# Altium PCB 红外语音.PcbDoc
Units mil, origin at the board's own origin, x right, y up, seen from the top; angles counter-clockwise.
Board outline 3936.84 x 3930.7 mil, 2 copper layers (Top Layer, Bottom Layer); 44 components, 33 nets, 149 pads, 170 vias.
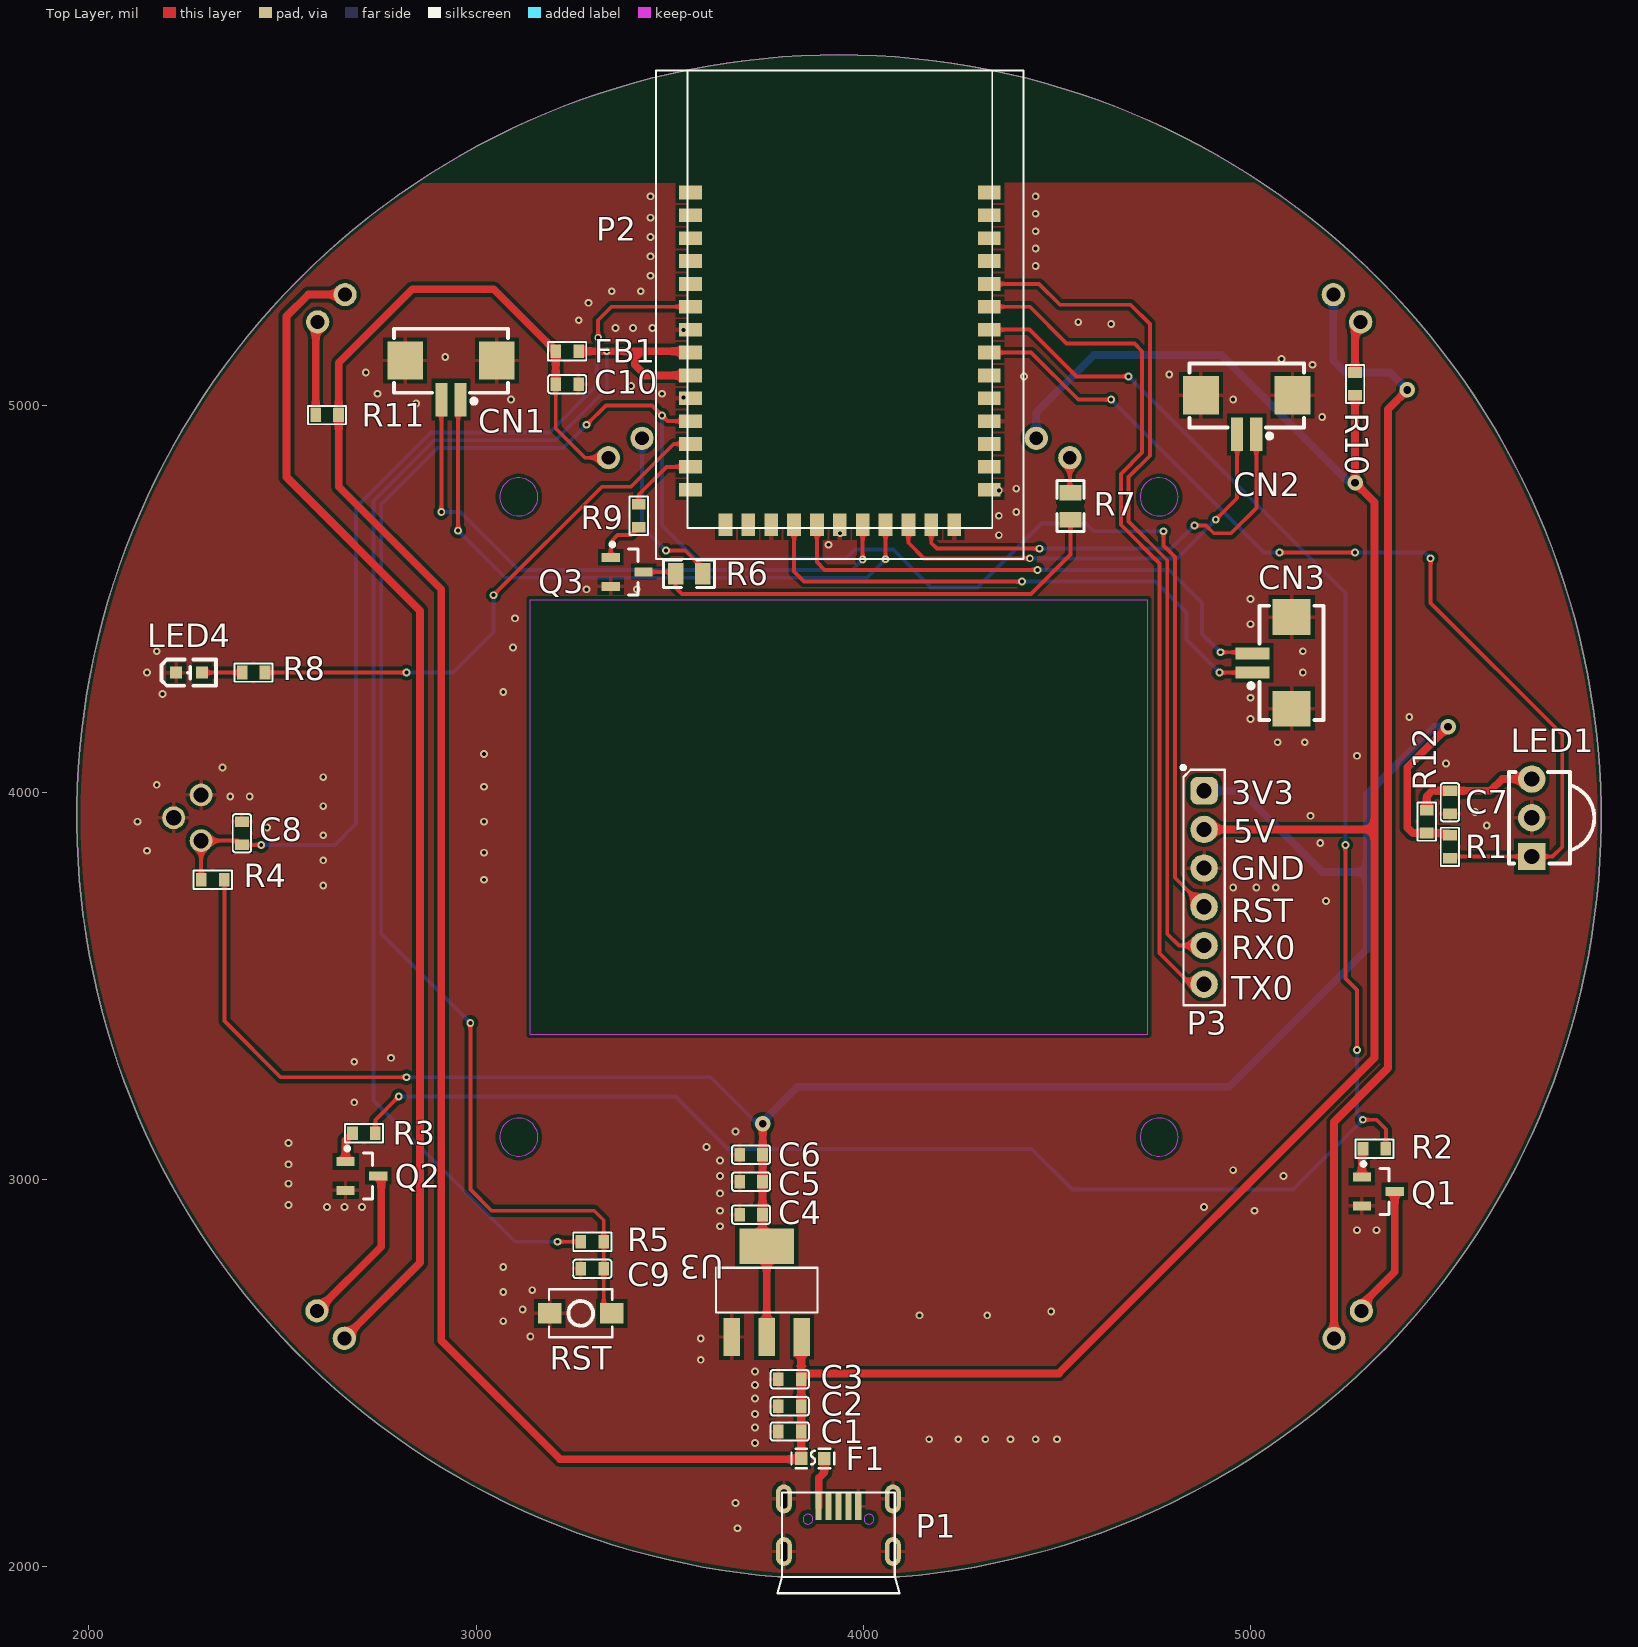
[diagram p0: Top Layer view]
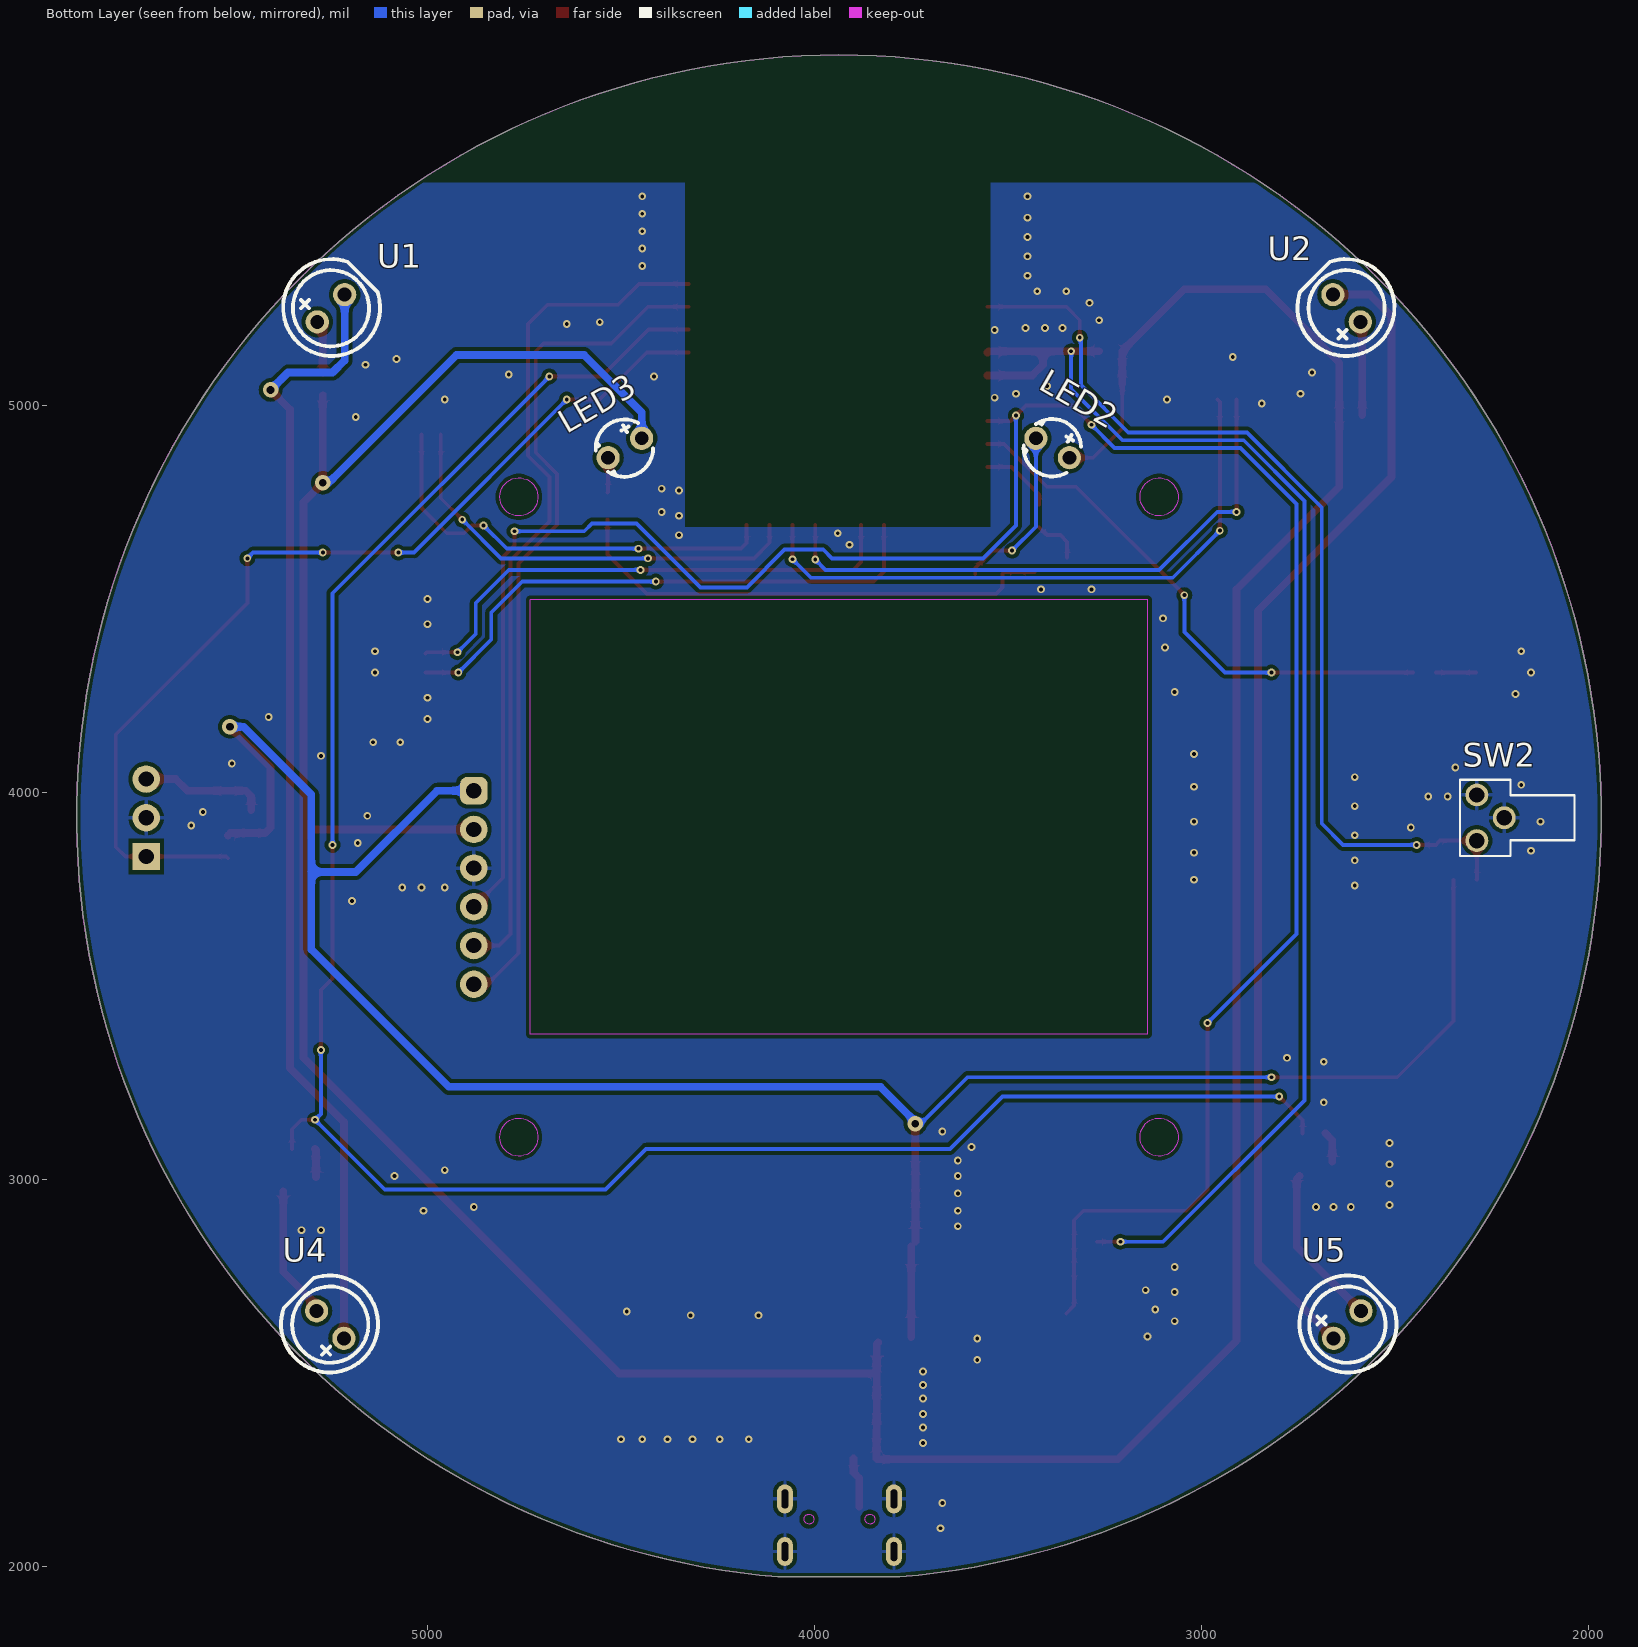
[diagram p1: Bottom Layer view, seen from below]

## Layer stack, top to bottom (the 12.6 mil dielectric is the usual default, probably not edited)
Top Solder: solder mask 0.4, Solder Resist, Dk 3.5
Top Layer: signal copper 1.4
Dielectric 1: dielectric 12.6, FR-4, Dk 4.8
Bottom Layer: signal copper 1.4
Bottom Solder: solder mask 0.4, Solder Resist, Dk 3.5

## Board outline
3779.51,1974.81 cw(c3937.01,3937.01) 4094.5,1974.81 4094.49,1974.81

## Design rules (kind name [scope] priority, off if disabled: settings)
Clearance [All] p1: gap=10
PolygonConnect [IsVia] p1: connectstyle=Direct reliefconductorwidth=10 reliefentries=4 polygonreliefangle="90 Angle" airgapwidth=10
PolygonConnect PolygonConnect_1 [All] p2: connectstyle=Relief reliefconductorwidth=10 reliefentries=4 polygonreliefangle="90 Angle" airgapwidth=10
RoutingVias [All] p1: holewidth=28 width=50 viastyle="Through Hole" minholewidth=28 minwidth=50 maxholewidth=28 maxwidth=50
SolderMaskExpansion [All] p1: expansion=4
Width [All] p1: maxlimit=50 minlimit=10 preferedwidth=10
30 further rules are at their usual default settings.

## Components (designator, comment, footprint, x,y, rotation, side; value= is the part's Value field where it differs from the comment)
C1 "22uF/6.3V" C0603_GRM18 3810,2350 r0 top
C2 "10uF/6.3V" C0603_GRM18 3810,2415 r0 top
C3 "100nF/25V" C0603_GRM18 3810,2485 r0 top
C4 "10uF/6.3V" C0603_GRM18 3710,2910 r0 top
C5 "100nF/25V" C0603_GRM18 3710,2995 r0 top
C6 "22uF/6.3V" C0603_GRM18 3710,3065 r0 top
C7 "4.7uF/10V" C0603_GRM18 5515,3975 r90 top
C8 "0.1uF/16V" C0603_GRM18 2395,3895 r270 top
C9 "0.1uF/16V" C0603_GRM18 3300,2770 r0 top
C10 "22uF/6.3V" C0603_GRM18 3235,5055 r180 top
CN1 "HC-1.25-2PWT" CONN-SMD_2P-P1.25-HC-1.25-2PWT 2935,5090 r180 top
CN2 "HC-1.25-2PWT" CONN-SMD_2P-P1.25-HC-1.25-2PWT 4990,5000 r180 top
CN3 "HC-1.25-2PWT" CONN-SMD_2P-P1.25-HC-1.25-2PWT 5080,4335 r90 top
F1 "BSMD0603L-150" F0603 3870,2280 r180 top
FB1 "100Mhz/1500mA" FB0603-H95 3235,5140 r0 top
LED1 "IRM-3638T-X" OPTO-TH_3P_IRM-36XXT 5775,3935 r90 top locked
LED2 "TZ-L2-03YYBW4TDJ40-001" LED-TH_BD3.8-P2.54-RD 3385,4890 r210 bottom locked
LED3 "TZ-L2-03YYBW4TDJ40-001" LED-TH_BD3.8-P2.54-RD 4490,4890 r150 bottom locked
LED4 "FC-F1608BK-470H5" LED0603-R-RD 2257.5,4310 r0 top
P1 "E-SMXXXXX" MIRCOUSB_5PIN 3935.75,2107.91 r0 top locked
P2 "VWRK2_ES-PCBA" VWXR2-ES-PCBA 3939.17,5120.87 r0 top locked
P3 "PH2.54-1x6p" HDR254-1x6-M-H885 4880,3755 r270 top
Q1 "S8050" SOT23-3 5330,2970 r0 top
Q2 "S8050" SOT23-3 2705,3010 r0 top
Q3 "S8050" SOT23-3 3390,4570 r0 top
R1 "10k" R0603 5515,3860 r270 top
R2 "1K/1%" R0603 5320,3080 r180 top
R3 "1K/1%" R0603 2710,3120 r180 top
R4 "10k/1%" R0603 2319.53,3775 r0 top
R5 "10k/1%" R0603 3300,2840 r180 top
R6 "120R" R0805 3550,4565 r0 top
R7 "120R" R0805 4535,4740 r90 top
R8 "1K/1%" R0603 2425,4310 r180 top
R9 "1K/1%" R0603 3420,4715 r270 top
R10 "20R" R0603 5270,5055.47 r270 top
R11 "20R" R0603 2615,4975 r0 top
R12 "47R" R0603 5455,3925 r270 top
RST "TS-1088-AR02016" SW-SMD_L4.0-W2.9-LS5.0 3270,2655 r0 top (schematic designator SW1)
SW2 "TS4570E-250AH" SW-3-4.5X4.5X7 2270,3935 r270 bottom locked
U1 "IR333-A_C264290" LED-TH_BD6.2-P2.54-FD 5250,5250 r135 bottom locked
U2 "IR333-A_C264290" LED-TH_BD6.2-P2.54-FD 2625,5250 r45 bottom
U3 "AMS1117-3.3" SOT-223-3_L6.5-W3.4-P2.30-LS7.0-BR 3805,2765 r270 top
U4 "IR333-A_C264290" LED-TH_BD6.2-P2.54-FD 5250,2625 r45 bottom locked
U5 "IR333-A_C264290" LED-TH_BD6.2-P2.54-FD 2625,2625 r135 bottom locked

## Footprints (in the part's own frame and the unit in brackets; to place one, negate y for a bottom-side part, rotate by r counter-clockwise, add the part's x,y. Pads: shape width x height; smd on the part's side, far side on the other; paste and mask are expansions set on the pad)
C0603_GRM18 [mm] "适用Murata GRM15封装"
  rect 0.7x0.9 smd paste+0 mask+0.051: 1(-0.75,0) 2(0.75,0)
  Top Layer pour cut-out: -0.254,0.602 0.254,0.602 0.254,-0.602 -0.254,-0.602
  silkscreen extent -1.25,-0.6 1.25,0.6, body extent -0.8,-0.4 0.8,0.4, height 0.8
CONN-SMD_2P-P1.25-HC-1.25-2PWT [mm]
  rect 0.8x2.2 smd: 1(-0.625,1.905) 2(0.625,1.905)
  rect 2.35x2.5 smd: 3(-3.005,-0.665) 4(3.005,-0.665)
  silkscreen extent -3.75,-2.74 3.75,2.16
F0603 [mil]
  rect 31.75x34.02 smd: 1(-29.2,0) 2(30.11,0)
  silkscreen extent -55,-25 55,25
FB0603-H95 [mm]
  rect 0.7x0.9 smd paste+0 mask+0.051: 1(-0.75,0) 2(0.75,0)
  Top Layer pour cut-out: -0.313,0.602 -0.313,-0.602 0.315,-0.602 0.315,0.602
  silkscreen extent -1.25,-0.6 1.25,0.6, body extent -0.9,-0.48 0.9,0.47, height 0.97
HDR254-1x6-M-H885 [mm] "Connector; Header; 1x6 Position"
  rrect50% 1.8x1.8 hole 1 mask+0.051: 1(-6.35,0)
  round 1.8 hole 1 mask+0.051: 2(-3.81,0) 3(-1.27,0) 4(1.27,0) 5(3.81,0) 6(6.35,0)
  silkscreen extent -7.98,-1.49 7.72,1.35, body extent -7.62,-1.27 7.62,1.27, height 8.54
LED0603-R-RD [mm]
  rect 0.8x0.8 smd: 1(0.876,0) 2(-0.826,0)
  silkscreen extent -1.79,-0.86 1.79,0.86
LED-TH_BD3.8-P2.54-RD [mil]
  round 60 hole 35.43: 1(-50,0) 2(50,0)
  silkscreen extent -68,-74 63,74
LED-TH_BD6.2-P2.54-FD [mil]
  round 60 hole 36: 1(-48.68,0) 2(51.32,0)
  silkscreen extent -121,-125 116,125
MIRCOUSB_5PIN [mm]
  rect 0.4x1.778 smd mask+0.051: 1(-1.3,1.225) 2(-0.65,1.225) 3(0,1.225) 4(0.65,1.225) 5(1.3,1.225)
  oval 1.05x1.9 hole 0.45 slot 1.25 at 90 deg: G1(-3.575,1.725) G2(-3.575,-1.725) G3(3.575,-1.725) G4(3.575,1.725)
  Keep-Out Layer circle w0.076: c2,0.4 r0.325
  Keep-Out Layer circle w0.076: c-2,0.4 r0.325
  silkscreen extent -4,-4.46 4,2.14
OPTO-TH_3P_IRM-36XXT [mm]
  rect 1.8x1.8 hole 1: 1(-2.54,1.237)
  round 1.8 hole 1: 2(0,1.237) 3(2.54,1.237)
  silkscreen extent -3,-2.86 3,2.74
R0603 [mm]
  rect 0.7x0.9 smd paste+0 mask+0.051: 1(-0.75,0) 2(0.75,0)
  Top Layer pour cut-out: -0.315,-0.602 -0.315,0.602 0.324,0.602 0.324,-0.602
  silkscreen extent -1.25,-0.6 1.25,0.6, body extent -0.8,-0.4 0.8,0.4, height 0.45
R0805 [mil]
  rect 40x56 smd mask+2.01: 1(-35,0) 2(35,0)
  Top Layer pour cut-out: -19.69,-35.43 -19.69,35.43 19.69,35.43 19.69,-35.43
  silkscreen extent -66,-35 66,35, body extent -39,-25 39,25, height 22
SOT23-3 [mm] "SOT23"
  rect 1.2x0.6 smd mask+0.051: 1(-1.075,0.95) 2(-1.075,-0.95) 3(1.075,0)
  silkscreen extent -1.1,-1.5 0.7,1.92, body extent -1.4,-1.45 1.4,1.45, height 1.2
SOT-223-3_L6.5-W3.4-P2.30-LS7.0-BR [mm]
  rect 2.5x1.1 smd: 1(4.34,-3.684) 2(4.34,-1.384) 3(4.34,0.916)
  rect 2.34x3.6 smd: 4(-1.6,-1.384)
  silkscreen extent -0.2,-4.71 2.74,1.94
SW-3-4.5X4.5X7 [mm] "轻触开关-4.5x4.5x7mm-DIP 3pin-L=4mm-卧式"
  round 1.5 hole 1: 1(-1.5,-0.498) 2(1.5,-0.498) 3(0,1.302)
  silkscreen extent -2.5,-1.6 2.5,5.91, body extent -2.31,-1.46 2.3,5.54, height 4.48
SW-SMD_L4.0-W2.9-LS5.0 [mm]
  rect 1.53x1.36 smd: 1(-2.035,0) 2(2.035,0)
  silkscreen extent -2.08,-1.58 2.08,1.58
VWXR2-ES-PCBA [mm]
  rect 1.5x0.9 smd mask+0.051: 1(-9.8,10.9) 2(-9.8,9.4) 3(-9.8,7.9) 4(-9.8,6.4) 5(-9.8,4.9) 6(-9.8,3.4) 7(-9.8,1.9) 8(-9.8,0.4) 9(-9.8,-1.1) 10(-9.8,-2.6) 11(-9.8,-4.1) 12(-9.8,-5.6) 13(-9.8,-7.1) 14(-9.8,-8.6) 26(9.8,-8.6) 27(9.8,-7.1) 28(9.8,-5.6) 29(9.8,-4.1) 30(9.8,-2.6) 31(9.8,-1.1) 32(9.8,0.4) 33(9.8,1.9) 34(9.8,3.4) 35(9.8,4.9) 36(9.8,6.4) 37(9.8,7.9) 38(9.8,9.4) 39(9.8,10.9)
  rect 0.9x1.5 smd mask+0.051: 15(-7.5,-10.9) 16(-6,-10.9) 17(-4.5,-10.9) 18(-3,-10.9) 19(-1.5,-10.9) 20(0,-10.9) 21(1.5,-10.9) 22(3,-10.9) 23(4.5,-10.9) 24(6,-10.9) 25(7.5,-10.9)
  silkscreen extent -12.05,-13.15 12.05,18.9, body extent -10,-11.1 10,18.9, height 3.6

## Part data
C1 C6 C10: library part 1.02.05.00885, "无极性电容"
C2 C4: library part 1.02.05.00861, "无极性电容"
C3 C5: library part 1.02.05.00915, "无极性电容"
C7: library part 1.02.05.00710, "无极性电容"
C8 C9: library part 1.02.05.00869, "无极性电容"
FB1: library part 1.04.03.00007, "磁珠"
P1: library part 1.14.03.00024, "USB"
P2: library part 2.05.04.00192
P3: library part 1.14.01.00027, "单排6pin"
Q1 Q2 Q3: library part 1.06.07.00232, "NPN  三极管"
R1: library part 1.01.01.01043, "电阻"
R2 R3 R8 R9: library part 1.01.01.00734, "电阻"
R4 R5: library part 1.01.01.01140, "电阻"
R6 R7: library part 1.01.01.01495, "电阻"
R10 R11: library part 1.01.01.01068, "电阻"
R12: library part 1.01.01.01739, "电阻"
SW2: library part 1.14.10.00254

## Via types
v1: diameter 20, hole 10, Top Layer to Bottom Layer, 166 vias
v2: diameter 40, hole 20, Top Layer to Bottom Layer, 4 vias

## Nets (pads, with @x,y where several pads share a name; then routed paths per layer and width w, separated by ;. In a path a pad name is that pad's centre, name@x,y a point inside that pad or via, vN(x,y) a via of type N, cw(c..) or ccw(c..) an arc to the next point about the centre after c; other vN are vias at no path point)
3V3: C4.2 C5.2 C6.2 P3.1 R1.1 R4.2 R12.2 U3.2 U3.4 | length 5764.5
  Top Layer w10: R4.2 2350,3774.06 2350,3410 2495,3265 v1(2820,3265)
  Top Layer w20: U3.4@3739.53,2840.47 3739.53,3030 3740,3030.47 v2(3740,3145) ; U3.2 U3.4 ; v2(5510,4170) 5405,4065 5405,3910 5419.53,3895.47 R12.2 5509.06,3895.47 R1.1
  Bottom Layer w10: v1(2820,3265) 3605,3265 3725,3145 v2(3740,3145)
  Bottom Layer w20: v2(3740,3145) 3740,3150 3830,3240 4945,3240 5300,3595 5300,3795 ; P3.1 4975,4005 5185,3795 5300,3795 ; v2(5510,4170) 5475,4170 5300,3995 5300,3795
5V: C1.2 C2.2 C3.2 C10.2 F1.2 FB1.1 LED2.2 LED3.2 P3.2 R10.2 R11.2 U3.3 | length 10150.2
  Top Layer w10: C10.2 3205.47,4940.47 3280.94,4865 LED2.2 ; R10.2@5265.94,5030 R10.2
  Top Layer w20: C10.2 FB1.1 3045.47,5300 2835,5300 2645,5110 2645,4790 2910,4525 2910,2585 3216.71,2278.29 3838.18,2278.29 F1.2 3839.89,2354.64 3839.53,2355 C3.2@3839.53,2500 ; U3.3@3835.55,2580 3839.53,2576.02 C3.2@3839.53,2500 ; P3.2 5320,3905 ; R10.2 v2(5270,4800) 5320,4750 5320,3905 ; C3.2@3839.53,2500 4505,2500 5320,3315 5320,3905
  Bottom Layer w10: v2@5255,4800 v2(5270,4800)
  Bottom Layer w20: LED3.2 4446.7,4981.7 4595,5130 4925,5130 v2@5255,4800
GND: C1.1 C2.1 C3.1 C4.1 C5.1 C6.1 C7.1 C8.1 C9.1 C10.1 CN1.3 CN1.4 CN2.3 CN2.4 CN3.3 CN3.4 LED1.2 LED4.2 P1.5 P1.G1 P1.G2 P1.G3 P1.G4 P2.7 P2.10 P2.17 P2.20 P2.25 P2.26 P2.29 P3.3 Q1.2 Q2.2 Q3.2 RST.1 SW2.1 SW2.3 U3.1
  other v1: 3675,2100 3670,2165 3720,2320 4170,2330 4245,2330 4315,2330 4380,2330 4445,2330 4500,2330 3720,2360 3720,2395 3720,2435 3720,2470 3720,2505 3580,2535 3580,2590 3140,2595 3070,2635 4145,2650 4320,2650 4485,2660 3120,2665 3070,2710 3145,2715 3070,2775 5275,2870 5325,2870 3630,2880 3630,2920 5010,2920 2615,2930 2660,2930 2705,2930 4880,2930 2515,2935 3630,2965 2515,2990 3630,3010 5085,3010 4955,3025 2515,3040 3630,3050 3595,3085 2515,3095 3670,3125 2685,3200 2685,3305 2780,3315 5195,3720 4955,3755 5015,3755 5065,3755 2605,3760 3020,3775 2605,3825 3020,3845 2150,3850 5180,3870 2605,3890 2460,3910 5610,3915 2125,3925 3020,3925 5155,3940 5580,3950 2605,3965 2365,3990 2415,3990 3020,4015 2175,4020 2605,4040 2345,4065 5505,4075 5275,4095 3020,4100 5070,4130 5140,4130 5000,4190 5410,4195 5000,4245 2190,4255 3070,4260 2150,4310 5135,4310 2175,4365 5135,4365 3095,4375 5000,4435 3100,4450 5000,4500 3285,4525 3415,4525 3910,4640 4350,4665 3940,4670 4350,4715 4395,4725 4350,4780 4395,4785 5185,4970 2845,5005 3090,5015 4955,5015 3535,5020 2745,5030 3480,5030 3400,5050 4415,5075 4790,5080 2715,5085 5160,5105 5080,5120 2920,5125 3535,5195 3360,5200 3405,5200 3455,5200 4640,5210 4555,5215 3265,5220 3290,5265 3350,5295 3425,5295 3450,5335 4445,5360 3450,5385 4445,5405 3450,5435 4445,5450 3450,5485 4445,5495 3450,5540 4445,5540
IR_RX: LED1.1 P2.32 R1.2 | length 2548.3
  Top Layer w10: P2.32 4433.39,5136.61 4555,5015 v1(4640,5015) ; v1(5075,4620) v1(5270,4620) ; v1(5465,4605) 5465,4490 5805,4150 5805,3860 5780,3835 LED1.1 5519.53,3835 R1.2
  Bottom Layer w10: v1(4640,5015) 5035,4620 v1(5075,4620) ; v1(5270,4620) 5450,4620 v1(5465,4605)
IR_TX: P2.33 R2.1 R3.1 | length 5484.8
  Top Layer w10: R3.1 2739.53,3154.53 v1(2800,3215) ; P2.33 4429.33,5195.67 4550,5075 v1(4685,5075) ; v1(5245,3865) 5245,3520 5275,3490 v1(5275,3335) ; v1(5290,3155) 5325,3155 5349.53,3130.47 R2.1
  Bottom Layer w10: v1(2800,3215) 3515,3215 3650,3080 4435,3080 4540,2975 5110,2975 v1(5290,3155) 5275,3170 v1(5275,3335) ; v1(4685,5075) 5245,4515 v1(5245,3865)
MIC1+: CN1.1 P2.22 | length 1604
  Top Layer w10: v1(2953.36,4676.64) 2953.36,5008.75 CN1.1 ; v1(4057.28,4602.72) P2.22
  Bottom Layer w10: v1(2953.36,4676.64) 3075,4555 4009.57,4555 v1(4057.28,4602.72)
MIC1-: CN1.2 P2.21 | length 1541.6
  Top Layer w10: v1(2910,4725) 2910,5014.61 CN1.2 ; v1(3998.23,4601.77) P2.21
  Bottom Layer w10: v1(2910,4725) 2960,4725 3110,4575 3971.46,4575 v1(3998.23,4601.77)
MIC2+: CN2.1 P2.24 | length 1143
  Top Layer w10: P2.24 4175.39,4644.61 4190,4630 v1(4455,4630) ; v1(4855,4690) 4885,4690 4905,4670 4950,4670 5015,4735 5015,4924.61 CN2.1
  Bottom Layer w10: v1(4455,4630) 4795,4630 v1(4855,4690)
MIC2-: CN2.2 P2.23 | length 1141.1
  Top Layer w10: P2.23 4116.34,4645.38 4156.72,4605 v1(4430,4605) ; v1(4910,4705) 4965.39,4760.39 CN2.2
  Bottom Layer w10: v1(4430,4605) 4810,4605 v1(4910,4705)
NetC7_2: C7.2 LED1.3 R12.1 | length 325.4
  Top Layer w20: R12.1 5455,3990 5469.53,4004.53 C7.2 5619.53,4004.53 5650,4035 LED1.3
NetF1_1: F1.1 P1.1 | length 129.9
  Top Layer w20: P1.1 3884.57,2229.57 3899.2,2244.2 F1.1
NetLED2_1: LED2.1 R6.2 | length 444.2
  Top Layer w10: v1(3490,4625) 3540,4625 3585,4580 R6.2
  Bottom Layer w10: LED2.1 3428.3,4686.7 v1(3490,4625)
NetLED3_1: LED3.1 R7.2 | length 90.7
  Top Layer w10: LED3.1 4533.3,4776.7 R7.2
NetLED4_1: LED4.1 R8.2 | length 103.5
  Top Layer w10: LED4.1 R8.2
NetQ1_1: Q1.1 R2.2 | length 73.8
  Top Layer w20: Q1.1 5287.68,3077.2 R2.2
NetQ1_3: Q1.3 U4.2 | length 344.3
  Top Layer w20: U4.2 5286.29,2676.29 5372.32,2762.32 Q1.3
NetQ2_1: Q2.1 R3.2 | length 80
  Top Layer w20: Q2.1 2662.68,3102.2 R3.2
NetQ2_3: Q2.3 U5.2 | length 420.8
  Top Layer w20: U5.2 2755,2827.57 2755,3002.32 Q2.3
NetQ3_1: Q3.1 R9.2 | length 128.3
  Top Layer w10: Q3.1 3347.68,4647.68 3365,4665 3399.53,4665 R9.2
NetQ3_3: Q3.3 R6.1 R7.1 | length 1278.8
  Top Layer w10: Q3.3 3510,4570 R6.1 3515,4530 3531.72,4513.28 4433.28,4513.28 4535,4615 R7.1
NetR10_1: R10.1 U1.1 | length 135
  Top Layer w10: U1.1@5259.42,5215.58 5259.42,5205.22 U1.1@5270,5194.64
  Top Layer w20: R10.1 U1.1@5270,5194.64
NetR11_1: R11.1 U2.1 | length 242.7
  Top Layer w10: U2.1@2585.47,5210.47 U2.1
  Top Layer w20: R11.1 U2.1@2585.47,5210.47
NetU1_2: U1.2 U4.1 | length 2920.8
  Top Layer w20: U4.1 5215.58,3149.42 5355,3288.85 5355,4990 v2(5405,5040)
  Bottom Layer w20: U1.2 5213.71,5116.29 5245,5085 5360,5085 v2(5405,5040)
NetU2_2: U2.2 U5.1 | length 3037.9
  Top Layer w20: U5.1 2855,2786.15 2855,4470 2510,4815 2510,5230 2566.29,5286.29 U2.2
PB17: C8.2 P2.6 R4.1 SW2.2 | length 2520
  Top Layer w10: R4.1 2289.61,3775.39 SW2.2 2384.53,3875.94 C8.2 2395.47,3865 v1(2445,3865) ; v1(3315,5175) 3315,5220 3349.72,5254.72 P2.6
  Bottom Layer w10: v1(2445,3865) 2635,3865 2690,3920 2690,4736.57 2883.43,4930 3190,4930 3312.26,5052.26 3312.26,5172.26 v1(3315,5175)
PWM0: P2.12 R8.1 | length 1399
  Top Layer w10: R8.1 v1(2820,4310) ; v1(3045,4510) 3325,4790 3400,4790 3510.39,4900.39 P2.12
  Bottom Layer w10: v1(2820,4310) 2940,4310 3045,4415 v1(3045,4510)
PWM1: P2.13 R9.1 | length 188.4
  Top Layer w10: R9.1 3420,4770 3491.34,4841.34 P2.13
RST: C9.2 P2.11 P3.4 R5.1 RST.2 | length 6166.6
  Top Layer w10: v1(2985,3405) 2985,2975 3040,2920 3305,2920 3329.53,2895.47 R5.1 C9.2 3329.53,2675.59 RST.2 ; v1(3285,4950) 3335,5000 3453.9,5000 v1(3480,4973.9) 3494.45,4959.45 P2.11 ; v1(4775,4675) 4775,4638.28 4805,4608.28 4805,3780 P3.4
  Bottom Layer w10: v1(2985,3405) 2755,3635 2755,4745 2900,4890 3225,4890 v1(3285,4950) ; v1(3480,4973.9) 3480,4690 3565,4605 3955,4605 3977.72,4627.72 4077.28,4627.72 4175,4530 4295,4530 4460,4695 4575,4695 4595,4675 v1(4775,4675)
RX0: P2.35 P3.5 | length 2179.6
  Top Layer w10: P2.35 4453.78,5313.78 4507.56,5260 4690,5260 4740,5210 4740,4870 4685,4815 4685,4700 4785,4600 4785,3635 4815,3605 P3.5@4855,3605
SPK+: CN3.1 P2.18 | length 1453.9
  Top Layer w10: P2.18 3821.06,4571.06 3847.13,4545 v1(4410,4545) ; v1(4920,4310) 5004.61,4310 CN3.1
  Bottom Layer w10: v1(4410,4545) 4755,4545 4835,4465 4835,4395 v1(4920,4310)
SPK-: CN3.2 P2.19 | length 1365.9
  Top Layer w10: P2.19 3880.12,4595.12 3900,4575.24 v1(4449.76,4575.24) ; v1(4922.5,4362.5) 5002.11,4362.5 CN3.2
  Bottom Layer w10: v1(4449.76,4575.24) 4564.76,4575.24 4565,4575 4790,4575 4875,4490 4875,4410 v1(4922.5,4362.5)
TX0: P2.34 P3.6 | length 2184.9
  Top Layer w10: P2.34 4430.28,5254.72 4525,5160 4700,5160 4720,5140 4720,4878.28 4665,4823.28 4665,4691.72 4765,4591.72 4765,3585 4845,3505 P3.6@4855,3505
VCC: FB1.2 P2.8 P2.9 R5.2 | length 3534.6
  Top Layer w10: v1(3210,2840) R5.2
  Top Layer w20: FB1.2 v1(3337.26,5140) 3410,5140 ; P2.9 3437.44,5077.56 3410,5105 3410,5140 ; P2.8 3549.96,5140 3410,5140
  Bottom Layer w10: v1(3210,2840) 3100,2840 2735,3205 2735,4753.28 2891.72,4910 3205,4910 3337.26,5042.26 v1(3337.26,5140)
pads on no net: P1.2 P1.3 P1.4 P2.1 P2.2 P2.3 P2.4 P2.5 P2.14 P2.15 P2.16 P2.27 P2.28 P2.30 P2.31 P2.36 P2.37 P2.38 P2.39

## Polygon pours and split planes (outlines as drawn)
GND on Bottom Layer "GND_L02_P000" (solid, remove dead copper, pour order 0): 3545,5575 3545,4685 4335,4685 4335,5575 5870,5575 6145,5300 6260,5185 6260,2360 6255,2360 5805,1910 5505,1610 2665,1610 2650,1610 1520,2740 1540,2760 1540,5575
GND on Top Layer "GND_L01_P002" (solid, remove dead copper, pour order 2): 3545,5575 3545,4685 4335,4685 4335,5575 5315,5575 5340,5575 6040,4875 6055,4860 6055,2770 6055,2740 5100,1785 5000,1685 2535,1685 2520,1685 1200,3005 1525,3330 1525,5570

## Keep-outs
Keep-Out Layer:
  circle w0.5: c3110.24,3110.24 r49.21
  circle w0.5: c3110.24,4763.78 r49.21
  circle w0.5: c4763.78,4763.78 r49.21
  circle w0.5: c4763.78,3110.24 r49.21
  lines w0.5: 3779.51,1974.81 cw(c3937.01,3937.01) 4094.5,1974.81 3779.53,1974.81 ; 3139.76,3375.98 4734.25,3375.98 4734.25,4498.03 3139.76,4498.03 3139.76,3375.98

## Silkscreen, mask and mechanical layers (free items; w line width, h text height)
Top Overlay:
  text "3V3" at 4950,3970 h60
  text "5V" at 4955,3870 h60
  text "GND" at 4950,3775 h60
  text "RST" at 4950,3665 h60
  text "RX0" at 4950,3570 h60
  text "TX0" at 4950,3465 h60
